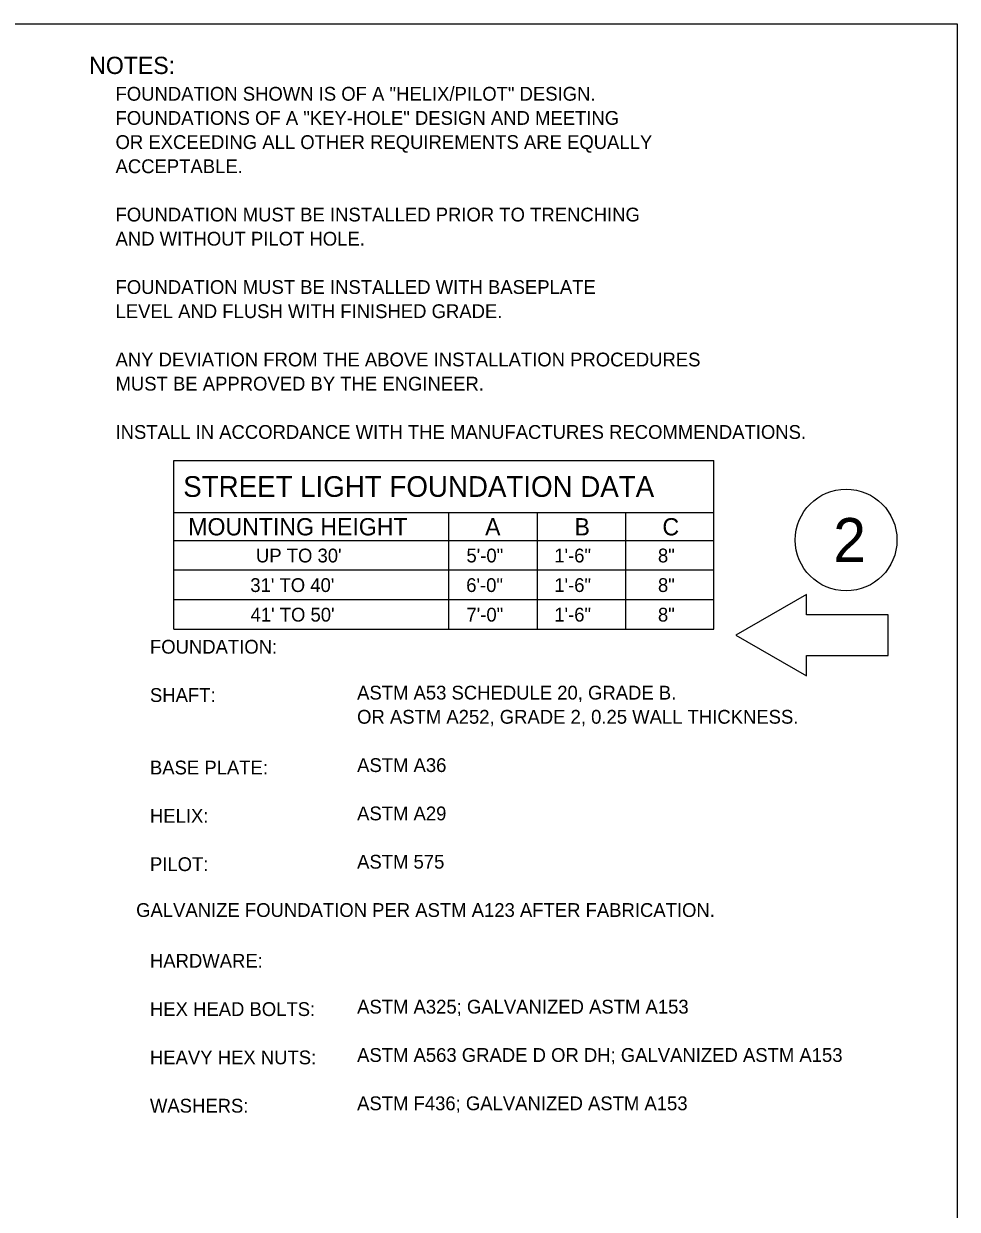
# Model space of a CAD drawing. Extents: x 99836 to 115004, y 99786 to 102182.
# Drawn here: x 102365 to 103176, y 101055 to 102086 of the extents above; entities that cross this region are included whole.
import ezdxf

# ---------------------------------------------------------------- set-up
doc = ezdxf.new("R2010")
doc.units = 0
for name, color, linetype in [('Border Organizer Shape', 7, 'Continuous'), ('Default', 7, 'Continuous'), ('Notes General Notes', 7, 'Continuous')]:
    doc.layers.add(name, color=color, linetype=linetype)

msp = doc.modelspace()

# ---------------------------------------------------------------- linework, layer by layer
at = {"layer": 'Border Organizer Shape'}
for p, q in [((102495.2, 101705.9), (102964.6, 101705.9)), ((102495.2, 101559.5), (102495.2, 101705.9)), ((102495.2, 101705.9), (102964.6, 101705.9)), ((102495.2, 101559.5), (102495.2, 101705.9)), ((102964.6, 101559.5), (102964.6, 101705.9)), ((102964.6, 101559.5), (102964.6, 101705.9)), ((102495.2, 101660.9), (102964.6, 101660.9)), ((102495.2, 101660.9), (102964.6, 101660.9)), ((102734.2, 101559.5), (102734.2, 101660.9)), ((102734.2, 101559.5), (102734.2, 101660.9)), ((102811.3, 101559.5), (102811.3, 101660.9)), ((102811.3, 101559.5), (102811.3, 101660.9)), ((102887.9, 101559.5), (102887.9, 101660.9)), ((102887.9, 101559.5), (102887.9, 101660.9)), ((102495.2, 101636.5), (102964.6, 101636.5)), ((102495.2, 101636.5), (102964.6, 101636.5)), ((102495.2, 101610.9), (102964.6, 101610.9)), ((102495.2, 101610.9), (102964.6, 101610.9)), ((102495.2, 101585.2), (102964.6, 101585.2)), ((102495.2, 101585.2), (102964.6, 101585.2)), ((102495.2, 101559.5), (102964.6, 101559.5)), ((102495.2, 101559.5), (102964.6, 101559.5))]:
    msp.add_line(p, q, dxfattribs=at)
at = {"layer": 'Default'}
msp.add_lwpolyline([(99976.3, 102085.7), (103176, 102085.7), (103176, 99886.1), (99976.3, 99886.1)], close=True, dxfattribs=at)
at = {"layer": 'Notes General Notes'}
msp.add_lwpolyline([(102983.5, 101554.1), (103045, 101518.7), (103045, 101536.4), (103115.9, 101536.4), (103115.9, 101571.9), (103045, 101571.9), (103045, 101589.6)], close=True, dxfattribs=at)
msp.add_circle((103079.4, 101636.9), 44.2, dxfattribs=at)

# ---------------------------------------------------------------- texts
at = {"layer": 'Border Organizer Shape'}
for s, height, p in [('NOTES:', 15, (102421.7, 102042)), ('FOUNDATION SHOWN IS OF A "HELIX/PILOT" DESIGN.', 12, (102444.6, 102018.8)), ('FOUNDATIONS OF A "KEY-HOLE" DESIGN AND MEETING', 12, (102444.6, 101997.8)), ('OR EXCEEDING ALL OTHER REQUIREMENTS ARE EQUALLY', 12, (102444.6, 101976.8)), ('ACCEPTABLE.', 12, (102444.6, 101955.8)), ('FOUNDATION MUST BE INSTALLED PRIOR TO TRENCHING', 12, (102444.6, 101913.8)), ('AND WITHOUT PILOT HOLE.', 12, (102444.6, 101892.8)), ('FOUNDATION MUST BE INSTALLED WITH BASEPLATE', 12, (102444.6, 101850.8)), ('LEVEL AND FLUSH WITH FINISHED GRADE.', 12, (102444.6, 101829.8)), ('ANY DEVIATION FROM THE ABOVE INSTALLATION PROCEDURES', 12, (102444.6, 101787.8)), ('MUST BE APPROVED BY THE ENGINEER.', 12, (102444.6, 101766.8)), ('INSTALL IN ACCORDANCE WITH THE MANUFACTURES RECOMMENDATIONS.', 12, (102444.6, 101724.8)), ('STREET LIGHT FOUNDATION DATA', 18, (102503.4, 101674.4)), ('STREET LIGHT FOUNDATION DATA', 18, (102503.4, 101674.4)), ('MOUNTING HEIGHT', 15, (102507.8, 101640.9)), ('MOUNTING HEIGHT', 15, (102507.8, 101640.9)), ('A', 15, (102765.7, 101640.9)), ('A', 15, (102765.7, 101640.9)), ('B', 15, (102843.4, 101640.9)), ('B', 15, (102843.4, 101640.9)), ('C', 15, (102919.8, 101640.9)), ('C', 15, (102919.8, 101640.9)), ("UP TO 30'", 12, (102566.6, 101617.4)), ("UP TO 30'", 12, (102566.6, 101617.4)), ('5\'-0"', 12, (102749.5, 101617.4)), ('5\'-0"', 12, (102749.5, 101617.4)), ('1\'-6"', 12, (102825.8, 101617.4)), ('1\'-6"', 12, (102825.8, 101617.4)), ('8"', 12, (102915.9, 101617.4)), ('8"', 12, (102915.9, 101617.4)), ("31' TO 40'", 12, (102561.7, 101591.7)), ("31' TO 40'", 12, (102561.7, 101591.7)), ('6\'-0"', 12, (102749.3, 101591.7)), ('6\'-0"', 12, (102749.3, 101591.7)), ('1\'-6"', 12, (102825.8, 101591.7)), ('1\'-6"', 12, (102825.8, 101591.7)), ('8"', 12, (102915.9, 101591.7)), ('8"', 12, (102915.9, 101591.7)), ("41' TO 50'", 12, (102561.9, 101566)), ("41' TO 50'", 12, (102561.9, 101566)), ('7\'-0"', 12, (102749.5, 101566)), ('7\'-0"', 12, (102749.5, 101566)), ('1\'-6"', 12, (102825.8, 101566)), ('1\'-6"', 12, (102825.8, 101566)), ('8"', 12, (102915.9, 101566)), ('8"', 12, (102915.9, 101566)), ('FOUNDATION:', 12, (102474.5, 101538.1)), ('SHAFT:', 12, (102474.5, 101496.1)), ('ASTM A53 SCHEDULE 20, GRADE B.', 12, (102654.5, 101498.2)), ('OR ASTM A252, GRADE 2, 0.25 WALL THICKNESS.', 12, (102654.5, 101477.2)), ('ASTM A36', 12, (102654.5, 101435.2)), ('BASE PLATE:', 12, (102474.5, 101433.1)), ('ASTM A29', 12, (102654.5, 101393.2)), ('HELIX:', 12, (102474.5, 101391.1)), ('PILOT:', 12, (102474.5, 101349.1)), ('ASTM 575', 12, (102654.5, 101351.2)), ('GALVANIZE FOUNDATION PER ASTM A123 AFTER FABRICATION.', 12, (102462.5, 101309.2)), ('HARDWARE:', 12, (102474.5, 101265.1)), ('HEX HEAD BOLTS:', 12, (102474.5, 101223.1)), ('ASTM A325; GALVANIZED ASTM A153', 12, (102654.5, 101225.2)), ('HEAVY HEX NUTS:', 12, (102474.5, 101181.1)), ('ASTM A563 GRADE D OR DH; GALVANIZED ASTM A153', 12, (102654.5, 101183.2)), ('WASHERS:', 12, (102474.5, 101139.1)), ('ASTM F436; GALVANIZED ASTM A153', 12, (102654.5, 101141.2))]:
    msp.add_text(s, height=height, dxfattribs=at).set_placement(p)
at = {"layer": 'Notes General Notes'}
msp.add_text('2', height=38.3, dxfattribs=at).set_placement((103068.2, 101617.7))

doc.saveas('drawing.dxf')
